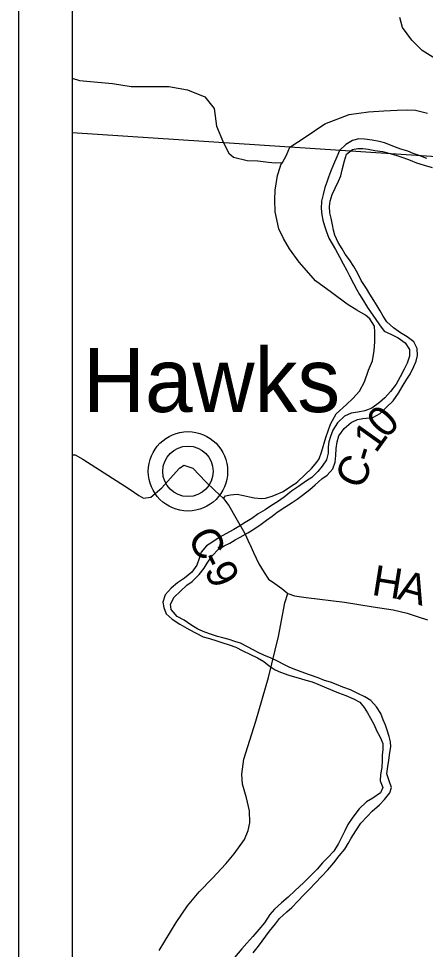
# Model space of a CAD drawing. Extents: x -15 to 405, y -40 to 87.
# Drawn here: x 8.195 to 8.957, y -24.755 to -23.012 of the extents above; entities that cross this region are included whole.
import ezdxf

# ---------------------------------------------------------------- set-up
doc = ezdxf.new("R2010")
doc.units = 0
for name, color, linetype in [('GM_P_State_Location', 7, 'Continuous'), ('GM_X_Major_Lake_Text', 7, 'Continuous'), ('GM_X_Minor_Lake', 7, 'Continuous'), ('GM_X_Rail_Line', 7, 'Continuous'), ('GM_X_Township', 7, 'Continuous'), ('GM_X_Township_Road', 7, 'Continuous'), ('GM_X_Township_ROW', 7, 'Continuous'), ('GM_X_Township_Subdivision_Text', 7, 'Continuous'), ('GM_X_Township_Text', 7, 'Continuous')]:
    doc.layers.add(name, color=color, linetype=linetype)

msp = doc.modelspace()

# ---------------------------------------------------------------- linework, layer by layer
at = {"layer": 'GM_P_State_Location'}
msp.add_lwpolyline([(8.458, -24.7568), (8.49, -24.7043), (8.5113, -24.6733), (8.5334, -24.6469), (8.5581, -24.6213), (8.5832, -24.5945), (8.5988, -24.5756), (8.6182, -24.5488), (8.6251, -24.5318), (8.6278, -24.5174), (8.6276, -24.4951), (8.6216, -24.4708), (8.6142, -24.445), (8.6128, -24.4264), (8.6167, -24.3987), (8.6393, -24.3272), (8.6632, -24.2455), (8.6817, -24.169), (8.6937, -24.1058), (8.6995, -24.0884)], dxfattribs=at)
at = {"layer": 'GM_X_Major_Lake_Text'}
for points in [[(8.2949, -23.1237), (8.3088, -23.1278), (8.371, -23.1336), (8.406, -23.1394), (8.476, -23.1394), (8.511, -23.1453), (8.544, -23.1589), (8.5615, -23.1803), (8.5654, -23.2133), (8.5784, -23.2449), (8.5887, -23.2639), (8.5973, -23.2716)], [(8.5973, -23.2716), (8.623, -23.2775), (8.6429, -23.2786), (8.6627, -23.281), (8.6756, -23.2821), (8.6891, -23.2813)]]:
    msp.add_lwpolyline(points, dxfattribs=at)
at = {"layer": 'GM_X_Rail_Line'}
msp.add_line((9.9329, -23.3338), (8.2949, -23.2262), dxfattribs=at)
at = {"layer": 'GM_X_Township'}
for p, q in [((8.1949, -19.033), (8.1949, -26.033)), ((8.2949, -19.133), (8.2949, -25.933))]:
    msp.add_line(p, q, dxfattribs=at)
at = {"layer": 'GM_X_Township_Road'}
for points in [[(8.9593, -23.2741), (8.9453, -23.2687), (8.9343, -23.2644), (8.9241, -23.2602), (8.9109, -23.2563), (8.901, -23.2528), (8.8806, -23.245), (8.87, -23.2423), (8.8571, -23.2399), (8.8427, -23.2379), (8.8325, -23.2375), (8.8203, -23.2401), (8.8081, -23.2479), (8.7959, -23.2592), (8.7909, -23.271), (8.7847, -23.2853), (8.7789, -23.2989), (8.7754, -23.3088), (8.7723, -23.3186), (8.7688, -23.3285), (8.7653, -23.3413), (8.7625, -23.3538), (8.7617, -23.3675), (8.7631, -23.3796), (8.7649, -23.3895), (8.7679, -23.3998), (8.7709, -23.4093), (8.7761, -23.423), (8.7824, -23.434), (8.7884, -23.4443), (8.7959, -23.458), (8.803, -23.471), (8.8098, -23.4839), (8.8146, -23.4934), (8.8221, -23.5083), (8.8277, -23.5186), (8.8333, -23.5285), (8.8412, -23.5407), (8.8483, -23.5528), (8.8551, -23.5628), (8.8626, -23.5734), (8.8708, -23.5852), (8.8799, -23.5971), (8.8931, -23.6036), (8.9056, -23.6098), (8.9192, -23.619), (8.927, -23.6319), (8.9273, -23.6441), (8.923, -23.6569), (8.9173, -23.6687), (8.9099, -23.683), (8.9019, -23.6966), (8.8915, -23.7102), (8.8808, -23.7223), (8.8709, -23.7309), (8.8568, -23.7414), (8.8434, -23.7467), (8.8305, -23.7492), (8.818, -23.751), (8.8054, -23.7566), (8.7924, -23.7687), (8.7832, -23.7826), (8.779, -23.7944), (8.7762, -23.8042), (8.7746, -23.8137), (8.7746, -23.8254), (8.7718, -23.8383), (8.7634, -23.85), (8.7553, -23.8602), (8.7439, -23.8715), (8.7343, -23.8775), (8.7195, -23.888), (8.7061, -23.897), (8.6924, -23.9079), (8.6798, -23.9169), (8.6687, -23.9237), (8.6569, -23.9316), (8.6439, -23.9394), (8.6317, -23.9477), (8.6195, -23.9556), (8.6077, -23.9627), (8.5978, -23.9683), (8.5833, -23.9766), (8.5708, -23.9837), (8.557, -23.9931)], [(8.5801, -23.9993), (8.5904, -23.9941), (8.6007, -23.9881), (8.6102, -23.9828), (8.624, -23.9746), (8.6354, -23.9682), (8.6491, -23.9588), (8.6594, -23.9509), (8.6697, -23.9438), (8.6793, -23.9359), (8.6934, -23.9269), (8.7071, -23.9183), (8.717, -23.9119), (8.7269, -23.9044), (8.7403, -23.8935), (8.7506, -23.8848), (8.7632, -23.8739), (8.7727, -23.8668), (8.7835, -23.8547), (8.7881, -23.8422), (8.7889, -23.8301), (8.7898, -23.8172), (8.7918, -23.8043), (8.7945, -23.7933), (8.8049, -23.7794), (8.8179, -23.7685), (8.83, -23.7629), (8.8395, -23.761), (8.8585, -23.7589), (8.8722, -23.7514), (8.8841, -23.7394), (8.8963, -23.7277), (8.9067, -23.7133), (8.9132, -23.7013), (8.9224, -23.6873), (8.9286, -23.6775), (8.9355, -23.6635), (8.9394, -23.6533), (8.9421, -23.643), (8.9415, -23.6298), (8.9351, -23.6172), (8.923, -23.608), (8.9102, -23.6007), (8.8974, -23.5908), (8.8845, -23.5797), (8.8778, -23.569), (8.8722, -23.5591), (8.8666, -23.5496), (8.8606, -23.5397), (8.8527, -23.5278), (8.8467, -23.5172), (8.8369, -23.5023), (8.8302, -23.4894), (8.8227, -23.476), (8.8145, -23.4635), (8.8069, -23.4532), (8.8013, -23.4433), (8.7938, -23.4311), (8.7875, -23.4174), (8.7849, -23.4079), (8.7827, -23.398), (8.7801, -23.3858), (8.7779, -23.3756), (8.7773, -23.3638), (8.7785, -23.3539), (8.7824, -23.3415), (8.7881, -23.3294), (8.7943, -23.3165), (8.7982, -23.3063), (8.8013, -23.2953), (8.8056, -23.2783), (8.8091, -23.2658), (8.8206, -23.2571), (8.8304, -23.2553), (8.8399, -23.2554), (8.8498, -23.2566), (8.8623, -23.2593), (8.8767, -23.261), (8.8911, -23.2649), (8.9032, -23.2684), (8.9164, -23.2726), (8.9285, -23.2769), (8.9403, -23.2823), (8.9543, -23.2865), (8.9694, -23.2912)], [(8.557, -23.9931), (8.5467, -23.9991), (8.5368, -24.0111), (8.5333, -24.0229), (8.5286, -24.0353), (8.5191, -24.0482), (8.5057, -24.0598), (8.4927, -24.0681), (8.4809, -24.0786), (8.4694, -24.0907), (8.4651, -24.1047), (8.467, -24.1146), (8.4714, -24.1267), (8.4827, -24.1363), (8.4971, -24.1459), (8.5141, -24.1555), (8.5273, -24.1628), (8.5405, -24.1693), (8.5526, -24.1728), (8.5659, -24.1767), (8.5757, -24.1798), (8.5894, -24.1845), (8.6015, -24.1891), (8.6151, -24.1957), (8.6279, -24.2018), (8.6423, -24.2088), (8.654, -24.2157), (8.6642, -24.2237), (8.6755, -24.2314), (8.6854, -24.2356), (8.7012, -24.2414), (8.7119, -24.2442), (8.7232, -24.2477), (8.7331, -24.2508), (8.7448, -24.2539), (8.7554, -24.2578), (8.7834, -24.2701), (8.794, -24.2743), (8.8076, -24.279), (8.8223, -24.2852), (8.8344, -24.2917), (8.8419, -24.302), (8.8483, -24.3119), (8.8539, -24.3214), (8.8607, -24.3344), (8.8655, -24.3447), (8.8719, -24.3572), (8.8771, -24.3694), (8.8774, -24.3808), (8.8758, -24.3903), (8.8757, -24.4005), (8.8753, -24.4138), (8.8725, -24.4274), (8.872, -24.4388), (8.8769, -24.4513), (8.873, -24.4615), (8.8585, -24.4717), (8.8463, -24.4784), (8.8329, -24.4912), (8.8211, -24.5071), (8.8118, -24.5207), (8.8057, -24.5324), (8.7995, -24.5452), (8.7941, -24.5566), (8.7853, -24.5709), (8.7734, -24.583), (8.7639, -24.5928), (8.7539, -24.6045), (8.7405, -24.618), (8.7283, -24.6301), (8.713, -24.644), (8.6997, -24.6568), (8.6871, -24.6673), (8.6744, -24.6794), (8.6656, -24.6892), (8.6553, -24.7047), (8.6446, -24.7175), (8.6338, -24.7303), (8.6227, -24.7427), (8.6128, -24.7533), (8.5994, -24.7695)], [(8.6344, -24.761), (8.6443, -24.7486), (8.665, -24.7207), (8.6758, -24.7067), (8.6838, -24.6969), (8.6972, -24.6845), (8.7067, -24.6762), (8.7186, -24.6638), (8.7285, -24.6532), (8.74, -24.6415), (8.7503, -24.6306), (8.7622, -24.6178), (8.7744, -24.6054), (8.7851, -24.5925), (8.7955, -24.5793), (8.8058, -24.5669), (8.8123, -24.5563), (8.8181, -24.5465), (8.8266, -24.5329), (8.8361, -24.5182), (8.8476, -24.5057), (8.8572, -24.4956), (8.8709, -24.4839), (8.8801, -24.4737), (8.8905, -24.4613), (8.8936, -24.4515), (8.8891, -24.4393), (8.8847, -24.4256), (8.8863, -24.4119), (8.8883, -24.4006), (8.8906, -24.3862), (8.8919, -24.3756), (8.8916, -24.3657), (8.8893, -24.3562), (8.8856, -24.3444), (8.8823, -24.3345), (8.8778, -24.325), (8.8734, -24.3132), (8.8655, -24.3007), (8.8546, -24.2888), (8.8436, -24.2819), (8.8304, -24.2754), (8.8164, -24.2688), (8.8024, -24.2634), (8.7903, -24.2584), (8.7793, -24.2545), (8.7676, -24.251), (8.7559, -24.2464), (8.74, -24.2406), (8.7244, -24.2351), (8.7142, -24.2313), (8.7029, -24.2266), (8.6915, -24.2213), (8.681, -24.2155), (8.667, -24.2089), (8.6552, -24.2043), (8.6439, -24.1989), (8.6341, -24.1939), (8.6235, -24.1881), (8.6106, -24.1816), (8.6, -24.1785), (8.5891, -24.1746), (8.5773, -24.1715), (8.5675, -24.1688), (8.5561, -24.1649), (8.544, -24.161), (8.5308, -24.1552), (8.5176, -24.1472), (8.5047, -24.1384), (8.4922, -24.1314), (8.4806, -24.1185), (8.4795, -24.1082), (8.4865, -24.095), (8.4979, -24.0837), (8.5101, -24.0728), (8.5201, -24.066), (8.5334, -24.0528), (8.5423, -24.0411), (8.5484, -24.0313), (8.5576, -24.0181), (8.5691, -24.0053), (8.5801, -23.9993)]]:
    msp.add_lwpolyline(points, dxfattribs=at)
at = {"layer": 'GM_X_Township_Subdivision_Text'}
for radius in [0.0744, 0.0472]:
    msp.add_circle((8.5121, -23.8597), radius, dxfattribs=at)
at = {"layer": 'GM_X_Township_Text'}
for points in [[(8.9811, -23.0904), (8.9509, -23.0716), (8.9313, -23.0526), (8.914, -23.0286), (8.9088, -23.0104)], [(8.7032, -23.2531), (8.7032, -23.2531), (8.7316, -23.234), (8.7688, -23.2091), (8.8141, -23.1918), (8.8501, -23.1867), (8.8789, -23.1846), (8.9038, -23.1836), (8.9231, -23.1829), (8.9386, -23.1834), (8.9609, -23.1892)], [(8.7111, -23.8836), (8.7114, -23.8834), (8.7182, -23.8789), (8.7437, -23.8544), (8.7536, -23.8423), (8.7578, -23.8362), (8.7624, -23.8238), (8.7704, -23.7961), (8.7747, -23.784), (8.7789, -23.7712), (8.7827, -23.7644), (8.7896, -23.7523), (8.8093, -23.7346), (8.8211, -23.7233), (8.8333, -23.7093), (8.8428, -23.6919), (8.8505, -23.67), (8.8581, -23.6526), (8.8609, -23.6333), (8.8621, -23.617), (8.8625, -23.5992), (8.8618, -23.5878), (8.8528, -23.5741), (8.8449, -23.5672), (8.8287, -23.5577), (8.8106, -23.5469), (8.7812, -23.5252), (8.751, -23.503), (8.7386, -23.4889), (8.7205, -23.4684), (8.7025, -23.4432), (8.6912, -23.4235), (8.6822, -23.4056), (8.6752, -23.3737), (8.6746, -23.3514), (8.6754, -23.3332), (8.6801, -23.3059), (8.685, -23.2902), (8.6862, -23.2862), (8.6891, -23.2813), (8.6969, -23.2681), (8.7032, -23.2531)], [(8.2949, -23.8285), (8.3007, -23.8287), (8.3151, -23.8366), (8.4019, -23.8922), (8.42, -23.905), (8.4288, -23.9099), (8.4427, -23.908), (8.4631, -23.8905), (8.4956, -23.8541), (8.4972, -23.853), (8.4974, -23.8528)], [(8.4974, -23.8528), (8.5046, -23.848), (8.5213, -23.854), (8.5459, -23.8794), (8.5622, -23.8953), (8.5787, -23.9105)], [(8.5787, -23.9105), (8.5823, -23.9058), (8.5918, -23.9035), (8.6042, -23.9021), (8.616, -23.9052), (8.6273, -23.9075), (8.6364, -23.9091), (8.6504, -23.9107), (8.6576, -23.91), (8.6701, -23.9063), (8.6776, -23.9029), (8.6894, -23.898), (8.7111, -23.8836)], [(8.5787, -23.9105), (8.5886, -23.9236), (8.6018, -23.9464), (8.6187, -23.9761), (8.6277, -23.9955)], [(8.6277, -23.9955), (8.6278, -23.9957), (8.6351, -24.0114), (8.6449, -24.0331), (8.6546, -24.0491), (8.6633, -24.0613), (8.6746, -24.0697), (8.6882, -24.0788), (8.6995, -24.0884), (8.7115, -24.0926), (8.7335, -24.0961), (8.8053, -24.1045), (8.859, -24.1135), (8.8964, -24.1187), (8.9225, -24.1252), (8.9436, -24.1322), (8.961, -24.1376)]]:
    msp.add_lwpolyline(points, dxfattribs=at)

# ---------------------------------------------------------------- texts
at = {"layer": 'GM_X_Minor_Lake'}
for s, rotation, p in [('0', 46.5899, (8.883, -23.8005)), ('1', 54.4593, (8.864, -23.8274)), ('-', 73.3419, (8.8595, -23.8453)), ('C', 64.8525, (8.8364, -23.8961)), ('C', 298.1239, (8.5101, -23.9829)), ('-', 295.3781, (8.5317, -24.0234)), ('9', 295.0056, (8.5417, -24.0444)), ('H', 350.9653, (8.8546, -24.0906)), ('A', 344.5094, (8.9024, -24.0981))]:
    msp.add_text(s, height=0.0568, rotation=rotation, dxfattribs=at).set_placement(p)
at = {"layer": 'GM_X_Township_ROW'}
msp.add_text('Hawks', height=0.12, rotation=0, dxfattribs=at).set_placement((8.3157, -23.7487))

doc.saveas('drawing.dxf')
